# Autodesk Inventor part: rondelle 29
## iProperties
Shininess: 20.0
Angle Display Precision: 2
Document Length Units: 11269
Document Angle Units: 11279
Document Time Units: 11290
Document Mass Units: 11283
Document Length Units Precision: 3
Document Angle Units Precision: 2
Compacted: True
Created: 2002-04
Part Number: rondelle 29
Material: Par défaut
Document SubType Name: Modélisation
Designer: thchene
Density: 0.0
Volumn: 0.0
Area: 0.0
PropertySet Name: Model Information
Control State: 0
Master: False
Checked Out: False
Author: thchene
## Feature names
1. Extrusion2
2. Chanfrein1 [Chamfer]
